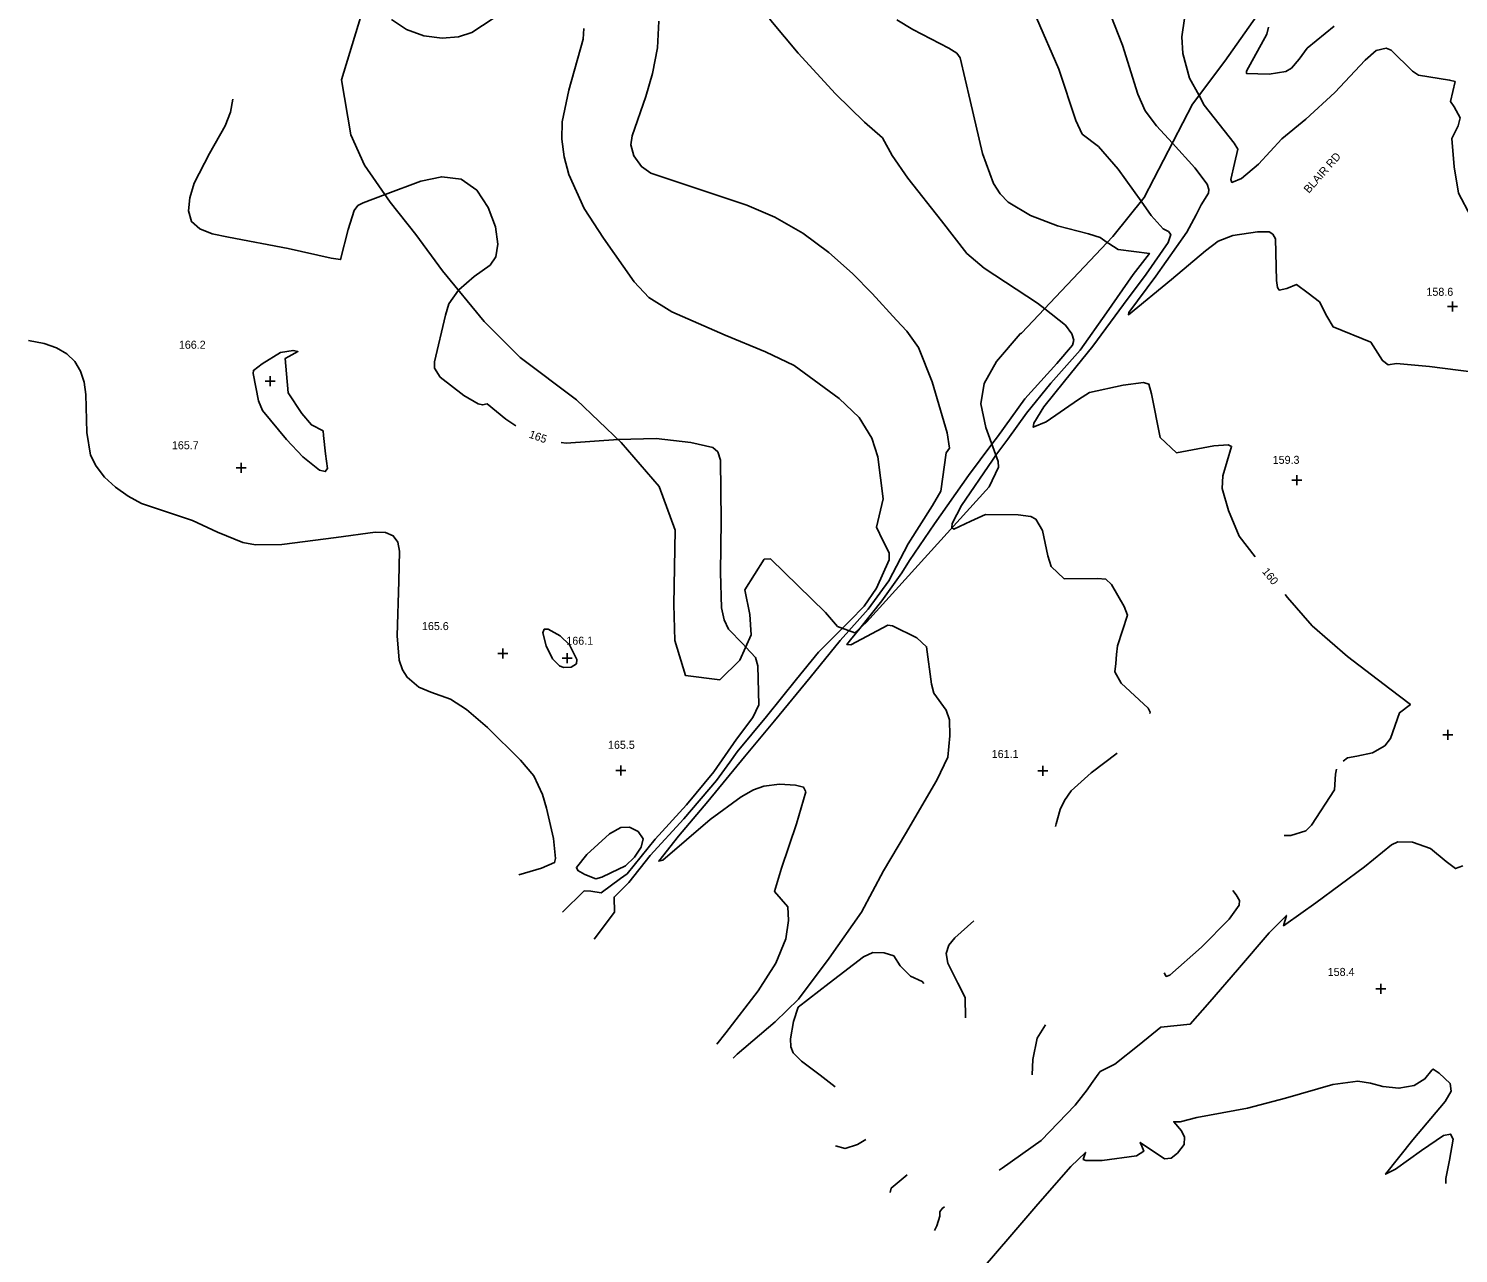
# Model space of a CAD drawing. Extents: x 1467615 to 2003689, y 770235 to 1108726.
# Drawn here: x 1999471.6 to 1999828.9, y 773778.4 to 774084.4 of the extents above; entities that cross this region are included whole.
import ezdxf

# ---------------------------------------------------------------- set-up
doc = ezdxf.new("R2010")
doc.units = 0
for name, color, linetype in [('RD_DTM_Major1', 7, 'Continuous'), ('RD_DTM_Major1_Lbl', 7, 'Continuous'), ('RD_DTM_Major2', 7, 'Continuous'), ('RD_DTM_Minor1', 7, 'Continuous'), ('RD_DTM_Minor2', 7, 'Continuous'), ('RD_DTM_Obscure', 7, 'Continuous'), ('RD_DTM_Spot_Elev', 7, 'Continuous'), ('RD_TX_Misc1', 7, 'Continuous')]:
    doc.layers.add(name, color=color, linetype=linetype)

msp = doc.modelspace()

# ---------------------------------------------------------------- linework, layer by layer
at = {"layer": 'RD_DTM_Major1'}
for points in [[(1999560.63, 774042.9), (1999555.19, 774040.85), (1999553.86, 774040.15), (1999552.92, 774038.92), (1999551.41, 774034.18), (1999549.52, 774026.68), (1999547.18, 774027.07), (1999536.41, 774029.44), (1999521.51, 774032.28), (1999517.47, 774033.14), (1999514.32, 774034.34), (1999512.28, 774036.16), (1999511.51, 774038.82), (1999511.82, 774042.11), (1999512.97, 774045.78), (1999516.74, 774053.17), (1999520.69, 774060.09), (1999522.04, 774063.47), (1999522.6, 774066.75)], [(1999778.05, 773952.38), (1999774.05, 773957.61), (1999771.41, 773963.97), (1999769.85, 773969.48), (1999770.01, 773972.67), (1999772.18, 773980), (1999771.29, 773980.41), (1999767.74, 773980.18), (1999758.4, 773978.41), (1999754.35, 773982.23), (1999752.14, 773993.16), (1999751.52, 773995.58), (1999750.16, 773995.97), (1999745.08, 773995.3), (1999736.71, 773993.46), (1999733.91, 773991.75), (1999725.87, 773986.14), (1999722.63, 773984.78), (1999722.72, 773985.79), (1999725.24, 773989.86), (1999730.41, 773996.34), (1999737.54, 774005.04), (1999745.14, 774015.42), (1999750.8, 774023.04), (1999756.29, 774030.91), (1999757.02, 774032.96), (1999756.43, 774033.66), (1999755.09, 774034.35), (1999752.09, 774037.68), (1999749.55, 774041.26)], [(1999593.35, 773985.11), (1999590.82, 773986.8), (1999586.18, 773990.62), (1999584.99, 773990.38), (1999583.93, 773990.61), (1999580.32, 773992.69), (1999574.4, 773997.32), (1999572.97, 773999.54), (1999573.01, 774001.13), (1999575.74, 774012.78), (1999576.54, 774015.63), (1999578.99, 774019.02)], [(1999618.88, 773981.75), (1999605.9, 773980.8), (1999604.61, 773980.97)], [(1999800.04, 773901.32), (1999801.16, 773902.2), (1999803.5, 773902.64), (1999807.4, 773903.44), (1999810.49, 773905.22), (1999811.85, 773907.01), (1999814.16, 773913.45), (1999816.85, 773915.49), (1999811.71, 773919.46), (1999801.14, 773927.52), (1999792.35, 773935.18), (1999786.15, 773942.23), (1999785.53, 773943)], [(1999604.96, 773863.63), (1999610.41, 773868.94), (1999612.1, 773868.89), (1999614.66, 773868.47), (1999619.46, 773872.03), (1999621.11, 773873.22), (1999628.11, 773881.84), (1999635.93, 773890.45), (1999642.78, 773898.71), (1999648.42, 773906.88), (1999652.58, 773912.29), (1999654.01, 773915.47), (1999653.82, 773925.2), (1999653.18, 773927.22), (1999650.77, 773929.87)], [(1999785.31, 773882.76), (1999786.95, 773882.82), (1999790.73, 773883.91), (1999792.17, 773885.38), (1999797.86, 773894.22), (1999798.18, 773898.09), (1999798.42, 773899.35)], [(1999755.34, 773848.44), (1999755.84, 773847.58), (1999756.73, 773847.88), (1999764.68, 773854.88), (1999771.61, 773861.91), (1999774.05, 773865.37), (1999774.19, 773866.55), (1999773.31, 773867.97), (1999772.51, 773869.08)], [(1999722.32, 773822.96), (1999722.48, 773826.78), (1999723.63, 773832.16), (1999725.71, 773835.45)], [(1999686.9, 773793.57), (1999687.11, 773794.67), (1999691.13, 773797.97)]]:
    msp.add_lwpolyline(points, dxfattribs=at)
at = {"layer": 'RD_DTM_Major2'}
for points in [[(1999749.55, 774041.26), (1999743.84, 774049.31), (1999738.9, 774054.96), (1999734.8, 774058.02), (1999733.29, 774061.4), (1999729.02, 774074.24), (1999723.4, 774087.09), (1999719.88, 774093.07), (1999716.04, 774097.99), (1999712.14, 774101.86), (1999705.4, 774106.94), (1999702.18, 774109.17)], [(1999578.99, 774019.02), (1999579.05, 774019.11), (1999582.88, 774022.47), (1999586.94, 774025.31), (1999588.32, 774027.38), (1999588.84, 774030.49), (1999588.21, 774034.84), (1999586.43, 774039.67), (1999583.55, 774043.99), (1999579.63, 774046.78), (1999574.82, 774047.36), (1999569.61, 774046.27), (1999560.63, 774042.9)], [(1999650.77, 773929.87), (1999650.04, 773930.68), (1999646.5, 773934.33), (1999645.38, 773936.67), (1999644.75, 773939.65), (1999644.44, 773948.5), (1999644.62, 773961.42), (1999644.44, 773976.59), (1999643.8, 773978.62), (1999642.51, 773979.69), (1999637.07, 773980.97), (1999628.41, 773981.96), (1999618.9, 773981.75), (1999618.88, 773981.75)]]:
    msp.add_lwpolyline(points, dxfattribs=at)
at = {"layer": 'RD_DTM_Minor1'}
for points in [[(1999797.8, 774084.97), (1999791.03, 774079.46), (1999789.04, 774076.75), (1999787.17, 774074.53), (1999785.7, 774073.7), (1999781.56, 774072.99), (1999775.88, 774073.21), (1999775.9, 774073.74), (1999781.01, 774082.98), (1999781.44, 774084.75)], [(1999832, 774037.43), (1999828.84, 774043.31), (1999827.81, 774049.87), (1999827.24, 774056.96), (1999828.79, 774060.09), (1999829.29, 774062.11), (1999827.8, 774064.88), (1999826.85, 774066.2), (1999828.02, 774071.17), (1999826.63, 774071.52), (1999818.89, 774072.79), (1999817.39, 774073.77), (1999812.04, 774078.98), (1999810.79, 774079.46), (1999808.31, 774078.88), (1999805.53, 774076.51), (1999797.97, 774068.44), (1999790.69, 774061.79), (1999784.77, 774056.83), (1999778.89, 774050.54), (1999774.67, 774046.9), (1999772.25, 774045.95), (1999772, 774046.7), (1999772.87, 774050.68), (1999773.72, 774054.26), (1999772.81, 774055.75), (1999765.3, 774065.3), (1999764.04, 774067.66)], [(1999832.74, 773998.56), (1999821.61, 773999.99), (1999813.35, 774000.7), (1999811.3, 774000.38), (1999809.9, 774001.45), (1999806.96, 774006.06), (1999797.56, 774009.87), (1999795.98, 774012.52), (1999794.11, 774016.11), (1999791.35, 774018.32), (1999788.38, 774020.45), (1999786, 774019.43), (1999784.09, 774019.04), (1999783.63, 774019.71), (1999783.38, 774021.49), (1999783.11, 774031.85), (1999782.5, 774033.01), (1999781.56, 774033.57), (1999778.67, 774033.59), (1999772.51, 774032.69), (1999768.81, 774031.25), (1999765.63, 774028.89), (1999757.12, 774021.72), (1999746.39, 774012.91), (1999746.46, 774013.43), (1999753.23, 774022.54), (1999761.02, 774033.52), (1999763.3, 774037.88), (1999764.61, 774040.36), (1999766.37, 774043.24), (1999766.48, 774044.22), (1999766.06, 774045.49), (1999763.02, 774049.59), (1999757.37, 774055.78)], [(1999713.3, 773977.77), (1999716.24, 773981.79), (1999720.93, 773988.3), (1999726.98, 773995.76), (1999734.33, 774004.07), (1999740.92, 774013.39), (1999747.58, 774022.91), (1999751.64, 774028.21), (1999743.87, 774029.16), (1999741.48, 774030.67), (1999741.09, 774030.96)], [(1999712.3, 773980.52), (1999713.71, 773982.38), (1999720.5, 773991.89), (1999728.53, 774000.69), (1999732.42, 774005.29), (1999732.74, 774006.54), (1999732.28, 774008.16), (1999730.64, 774010.28), (1999725.47, 774014.4)], [(1999594.08, 773872.94), (1999599.75, 773874.59), (1999603.01, 773876), (1999603.25, 773877.03), (1999602.72, 773882.03), (1999601, 773889.62), (1999599.98, 773893.06), (1999597.81, 773897.7), (1999594.48, 773901.59), (1999586.27, 773909.77), (1999581.01, 773914.28), (1999576.99, 773916.83), (1999572.07, 773918.63), (1999569.04, 773919.88), (1999566.18, 773922.33), (1999565.03, 773924.19), (1999564.2, 773926.57), (1999563.65, 773932.69), (1999564.08, 773946.33), (1999564.26, 773953.81), (1999563.8, 773956.05), (1999562.7, 773957.67), (1999560.78, 773958.47), (1999558.18, 773958.6), (1999548.42, 773957.22), (1999534.87, 773955.47), (1999528.29, 773955.43), (1999525.08, 773956.01), (1999518.77, 773958.56), (1999512.54, 773961.47), (1999499.8, 773965.71), (1999496.48, 773967.53), (1999493.32, 773969.79), (1999490.55, 773972.35), (1999488.42, 773975.05), (1999487.07, 773977.81), (1999486.12, 773983.51), (1999485.89, 773992.95), (1999485.43, 773996.03), (1999484.55, 773998.82), (1999483.12, 774001.2), (1999481.12, 774003.14), (1999478.57, 774004.64), (1999475.46, 774005.71), (1999471.57, 774006.43)], [(1999536.44, 773993.36), (1999536, 773998.11), (1999535.7, 774001.97), (1999536.56, 774002.5), (1999538.88, 774003.69), (1999537.67, 774003.99), (1999534.54, 774003.46), (1999529.95, 774000.65), (1999527.75, 773998.98), (1999527.67, 773998.24), (1999529, 773991.41), (1999530, 773988.93), (1999536, 773981.73), (1999540.06, 773977.39), (1999544.3, 773974.1), (1999545.68, 773973.72), (1999546.24, 773974.5), (1999545.79, 773978.15), (1999545.27, 773982.74), (1999545.16, 773983.87), (1999542.23, 773985.36), (1999539.84, 773988.26), (1999536.44, 773993.36)], [(1999751.74, 773913.28), (1999751.86, 773913.62), (1999751.31, 773914.58), (1999744.58, 773920.83), (1999742.97, 773923.66), (1999743.25, 773925.74), (1999743.38, 773928.01), (1999743.65, 773930.19), (1999746.13, 773937.86), (1999745.36, 773939.96), (1999742.17, 773945.49), (1999740.74, 773946.79), (1999738.71, 773947.03), (1999730.36, 773946.91), (1999727.12, 773950), (1999726.29, 773952.63), (1999724.95, 773959.01), (1999723.29, 773961.82), (1999722, 773962.52), (1999718.83, 773962.92), (1999710.72, 773963.01), (1999706.99, 773961.29), (1999702.75, 773959.36), (1999702.33, 773959.66)], [(1999605.2, 773924.77), (1999607.15, 773924.87), (1999608.47, 773925.69), (1999608.59, 773926.75), (1999606.75, 773930.45), (1999604.41, 773932.66), (1999601.43, 773934.35), (1999600.42, 773934.32), (1999600.07, 773933.44), (1999600.86, 773930.14), (1999602.47, 773926.96), (1999604.24, 773925.16), (1999605.2, 773924.77)], [(1999612.89, 773856.85), (1999617.94, 773863.63), (1999617.85, 773867.4), (1999620.12, 773869.65), (1999621.57, 773871.06), (1999626.91, 773877.75), (1999635.32, 773886.97), (1999643.45, 773896.54), (1999646.76, 773901.11), (1999648.59, 773903.69), (1999655.96, 773912.48), (1999663.43, 773921.88), (1999668.91, 773928.55), (1999674.97, 773934.56)], [(1999647.61, 773827.17), (1999648.6, 773828.18), (1999658.12, 773836.22), (1999663.99, 773841.92), (1999671.6, 773852.15), (1999679.7, 773863.64), (1999685.23, 773873.92), (1999690.71, 773883.16), (1999698.53, 773896.62), (1999701.24, 773902.36), (1999701.78, 773907.66), (1999701.71, 773911.7), (1999700.87, 773914.13), (1999697.77, 773918.37), (1999697.23, 773920.57), (1999695.94, 773929.96), (1999693.54, 773932.15), (1999687.41, 773935.17), (1999686.29, 773935.34), (1999677.03, 773930.43), (1999676.07, 773930.5), (1999676.98, 773931.64), (1999679.29, 773934.54)], [(1999643.51, 773830.67), (1999645.82, 773833.51), (1999653.88, 773843.94), (1999658.29, 773850.87), (1999660.79, 773856.95), (1999661.49, 773861.54), (1999661.29, 773865), (1999657.98, 773868.81), (1999659.7, 773874.58), (1999663.49, 773885.67), (1999665.76, 773893.73), (1999665.24, 773894.84), (1999663.24, 773895.33), (1999659.2, 773895.61), (1999655.31, 773895.12), (1999652.75, 773894.17), (1999649.64, 773892.47), (1999641.9, 773886.75), (1999630.03, 773876.62), (1999629.04, 773876.38), (1999633.93, 773882.58), (1999641.26, 773891.24), (1999650.44, 773902.41), (1999657.98, 773911.4), (1999666.83, 773922.29), (1999674.39, 773931.53), (1999676.57, 773933.95)], [(1999728.18, 773885.04), (1999728.34, 773885.68), (1999729.33, 773889.28), (1999730.43, 773891.55), (1999732.12, 773893.92), (1999737.11, 773898.42), (1999743.56, 773903.32)], [(1999610.53, 773873.06), (1999613.34, 773871.95), (1999614.81, 773872.37), (1999617.1, 773873.42), (1999620.71, 773875.23), (1999623.01, 773877.41), (1999624.66, 773879.84), (1999625.12, 773881.97), (1999623.88, 773883.79), (1999621.73, 773884.87), (1999619.55, 773884.82), (1999616.75, 773883.17), (1999611.07, 773878.03), (1999608.46, 773874.79), (1999608.8, 773874.01), (1999610.53, 773873.06)], [(1999714.06, 773799.15), (1999714.82, 773799.63), (1999724.63, 773806.61), (1999733.06, 773815.44), (1999736.08, 773819.27), (1999737.16, 773820.83), (1999738.8, 773823.11), (1999739.3, 773823.79), (1999743, 773825.67), (1999749.06, 773830.49), (1999754.53, 773834.88), (1999761.83, 773835.65), (1999766.71, 773841.21), (1999773.62, 773849.25), (1999781.53, 773858.43), (1999785.88, 773862.81), (1999785.19, 773860.24), (1999785.76, 773860.61), (1999793.2, 773865.94), (1999805.41, 773874.92), (1999812.12, 773880.47), (1999813.75, 773881.18), (1999817.37, 773881.1), (1999821.86, 773879.56), (1999825.79, 773876.32), (1999828.14, 773874.53), (1999830, 773875.21)], [(1999705.69, 773837.2), (1999705.57, 773842.31), (1999703.8, 773845.9), (1999701.3, 773850.89), (1999700.88, 773853.31), (1999701.52, 773855.39), (1999703, 773857.21), (1999707.74, 773861.44)], [(1999695.27, 773845.78), (1999694.89, 773846.29), (1999691.93, 773847.64), (1999689.35, 773850.23), (1999687.74, 773852.7), (1999685.36, 773853.48), (1999682.53, 773853.56), (1999680.17, 773852.44), (1999671.64, 773845.87), (1999663.85, 773839.89), (1999662.74, 773836.31), (1999661.95, 773831.97), (1999662.02, 773830), (1999662.58, 773828.47), (1999664.71, 773826.43), (1999669.39, 773822.94), (1999673.15, 773819.97)], [(1999709.59, 773774.18), (1999717.25, 773783.06), (1999723.74, 773790.64), (1999731.97, 773800.11), (1999735.7, 773803.59), (1999735.12, 773801.84), (1999735.79, 773801.56), (1999739.87, 773801.56), (1999748.44, 773802.73), (1999750.28, 773803.93), (1999749.76, 773805.16), (1999749.34, 773806.1), (1999755.4, 773801.97), (1999757.07, 773802.18), (1999758.67, 773803.42), (1999760.33, 773805.6), (1999760.44, 773807.4), (1999759.64, 773808.98), (1999757.72, 773811.26), (1999759.36, 773811.26), (1999763.51, 773812.34), (1999776.19, 773814.63), (1999785.61, 773817.16), (1999797.48, 773820.53), (1999803.73, 773821.4), (1999806.86, 773820.87), (1999809.94, 773820.03), (1999813.98, 773819.64), (1999817.82, 773820.35), (1999820.47, 773821.98), (1999822.22, 773824.16), (1999822.57, 773824.43), (1999824.03, 773823.43), (1999826.79, 773820.8), (1999827.02, 773818.94), (1999825.51, 773816.31), (1999817.45, 773806.77), (1999810.64, 773798.14), (1999813.16, 773799.42), (1999819.63, 773804.11), (1999825.13, 773807.82), (1999826.9, 773808.18), (1999827.51, 773806.92), (1999826.59, 773801.65), (1999825.75, 773797.11), (1999825.7, 773795.83)], [(1999673.24, 773805.26), (1999675.62, 773804.61), (1999678.66, 773805.54), (1999680.79, 773806.82)], [(1999697.96, 773784.12), (1999698.5, 773785.22), (1999699.28, 773787.71), (1999699.28, 773788.74), (1999699.88, 773789.61), (1999700.41, 773790.02)]]:
    msp.add_lwpolyline(points, dxfattribs=at)
at = {"layer": 'RD_DTM_Minor2'}
for points in [[(1999725.47, 774014.4), (1999723.69, 774015.83), (1999710.39, 774024.54), (1999706.01, 774028.2), (1999699.65, 774036.37), (1999691.26, 774047.01), (1999687.39, 774052.7), (1999684.95, 774057.09), (1999680.46, 774061.03), (1999673.23, 774068.13), (1999663.86, 774078.28), (1999657.01, 774086.4), (1999653.43, 774092.06), (1999647.74, 774104.43), (1999640.9, 774118.93), (1999636.16, 774126.49), (1999633.18, 774129.85), (1999625.81, 774136.1), (1999619.01, 774141.59), (1999616.76, 774144.07), (1999615.23, 774146.92), (1999614.17, 774150.74), (1999612.53, 774163.5), (1999611.77, 774172.12)], [(1999757.37, 774055.78), (1999753.43, 774060.09), (1999750.57, 774063.86), (1999748.72, 774067.97), (1999744.88, 774080.24), (1999740.04, 774092.84)], [(1999590.53, 774088.84), (1999582.3, 774083.42), (1999578.99, 774082.34), (1999574.87, 774082.04), (1999570.34, 774082.61), (1999565.96, 774084.13), (1999562.28, 774086.64)], [(1999674.97, 773934.56), (1999676.8, 773936.38), (1999680.34, 773940.1), (1999683.41, 773944.56), (1999686.59, 773951.68), (1999686.6, 773953.38), (1999685.06, 773956.53), (1999683.45, 773959.83), (1999685.11, 773966.94), (1999683.79, 773977.4), (1999682.29, 773982.04), (1999679.13, 773987.2), (1999674.15, 773991.93), (1999662.9, 774000.2), (1999655.71, 774003.65), (1999645.6, 774007.82), (1999632.28, 774013.64), (1999626.53, 774017.23), (1999622.92, 774021.16), (1999615.19, 774032.02), (1999610.38, 774039.41), (1999606.6, 774047.92), (1999605.4, 774052.36), (1999604.83, 774056.78), (1999604.93, 774061.06), (1999606.53, 774069.03), (1999610.18, 774081.71), (1999610.31, 774084.4)], [(1999676.57, 773933.95), (1999681.39, 773939.3), (1999686.56, 773946.4), (1999691.33, 773955.68), (1999697.48, 773965.22), (1999699.48, 773968.81), (1999700.88, 773978.39), (1999701.65, 773979.54), (1999701.11, 773983.39), (1999697.36, 773996.15), (1999693.97, 774004.72), (1999691.02, 774008.77), (1999688.43, 774011.53), (1999682.34, 774018.23), (1999677.43, 774023.21), (1999671.57, 774028.46), (1999665, 774033.31), (1999658.01, 774037.25), (1999651.01, 774040.3), (1999638.84, 774044.34), (1999627.06, 774048.25), (1999624.69, 774049.92), (1999622.8, 774052.64), (1999622.06, 774055.35), (1999622.4, 774057.56), (1999625.79, 774067.42), (1999627.47, 774073.15), (1999628.72, 774079.58), (1999629.03, 774086.28)], [(1999741.09, 774030.96), (1999739.37, 774032.21), (1999736.4, 774033.09), (1999728.66, 774035.08), (1999721.9, 774037.73), (1999716.36, 774041.06), (1999714.36, 774043.11), (1999712.72, 774045.69), (1999709.97, 774053.2), (1999706.89, 774066.41), (1999704.36, 774077.1), (1999703.56, 774078.25), (1999701.51, 774079.54), (1999692.51, 774084.13), (1999688.51, 774086.62)], [(1999764.04, 774067.66), (1999761.69, 774072.04), (1999759.97, 774078.13), (1999759.74, 774082.36), (1999760.4, 774086.89)], [(1999679.29, 773934.54), (1999684.76, 773941.42), (1999689.79, 773948.44), (1999691.68, 773951.51), (1999697.95, 773960.67), (1999706.45, 773972.76), (1999712.3, 773980.52)], [(1999702.33, 773959.66), (1999702.25, 773959.71), (1999702.37, 773960.77), (1999704.72, 773965.26), (1999712.44, 773976.59), (1999713.3, 773977.77)]]:
    msp.add_lwpolyline(points, dxfattribs=at)
at = {"layer": 'RD_DTM_Obscure'}
msp.add_lwpolyline([(1999778.48, 774087.59), (1999770.49, 774076.22), (1999762.45, 774065.54), (1999750.29, 774042.19), (1999742.52, 774032.47), (1999719.71, 774008.3), (1999719.32, 774008.13), (1999713.46, 774001.19), (1999710.31, 773995.71), (1999709.5, 773990.65), (1999710.75, 773984.69), (1999712.88, 773978.96), (1999713.86, 773976.19), (1999713.96, 773974.84), (1999711.61, 773969.88), (1999680.94, 773936.09), (1999678.07, 773933.39), (1999673.74, 773935.02), (1999670.69, 773938.5), (1999656.93, 773951.92), (1999655.39, 773951.82), (1999650.55, 773944.15), (1999651.79, 773938), (1999652.12, 773932.88), (1999649.31, 773926.61), (1999644.27, 773921.65), (1999635.68, 773922.79), (1999633.07, 773931.53), (1999632.79, 773940.5), (1999633.14, 773959.05), (1999629.14, 773969.99), (1999619.66, 773981), (1999608.52, 773991.64), (1999594.4, 774002.18), (1999585.37, 774011.24), (1999575.03, 774023.84), (1999568.32, 774032.94), (1999561.92, 774041.06), (1999555.5, 774050.23), (1999552.05, 774057.86), (1999549.78, 774071.58), (1999554.54, 774087.14)], dxfattribs=at)
at = {"layer": 'RD_DTM_Spot_Elev'}
for p, q in [((1999826.13, 774014.92), (1999828.63, 774014.92)), ((1999827.38, 774013.67), (1999827.38, 774016.17)), ((1999530.69, 773996.29), (1999533.19, 773996.29)), ((1999531.94, 773995.04), (1999531.94, 773997.54)), ((1999523.44, 773974.64), (1999525.94, 773974.64)), ((1999524.69, 773973.39), (1999524.69, 773975.89)), ((1999787.22, 773971.6), (1999789.72, 773971.6)), ((1999788.47, 773970.35), (1999788.47, 773972.85)), ((1999588.81, 773928.28), (1999591.31, 773928.28)), ((1999590.06, 773927.03), (1999590.06, 773929.53)), ((1999606.15, 773925.8), (1999606.15, 773928.3)), ((1999604.9, 773927.05), (1999607.4, 773927.05)), ((1999826.24, 773906.72), (1999826.24, 773909.22)), ((1999824.99, 773907.97), (1999827.49, 773907.97)), ((1999618.29, 773899.01), (1999620.79, 773899.01)), ((1999619.54, 773897.76), (1999619.54, 773900.26)), ((1999723.72, 773898.91), (1999726.22, 773898.91)), ((1999724.97, 773897.66), (1999724.97, 773900.16)), ((1999809.43, 773843.23), (1999809.43, 773845.73)), ((1999808.18, 773844.48), (1999810.68, 773844.48))]:
    msp.add_line(p, q, dxfattribs=at)

# ---------------------------------------------------------------- texts
at = {"layer": 'RD_DTM_Major1_Lbl'}
for s, rotation, p in [('165', 340.4626, (1999596.44, 773982.24)), ('160', 308.7553, (1999779.68, 773948.69))]:
    msp.add_text(s, height=2, rotation=rotation, dxfattribs=at).set_placement(p)
at = {"layer": 'RD_DTM_Spot_Elev'}
for s, p in [('158.6', (1999820.87, 774017.63)), ('166.2', (1999509.12, 774004.4)), ('165.7', (1999507.38, 773979.29)), ('159.3', (1999782.45, 773975.64)), ('165.6', (1999569.86, 773934.11)), ('166.1', (1999605.94, 773930.45)), ('165.5', (1999616.35, 773904.44)), ('161.1', (1999712.24, 773902.15)), ('158.4', (1999796.2, 773847.7))]:
    msp.add_text(s, height=2, dxfattribs=at).set_placement(p)
at = {"layer": 'RD_TX_Misc1'}
msp.add_text('BLAIR RD', height=2, rotation=48.6914, dxfattribs=at).set_placement((1999791.49, 774043.09))

doc.saveas('drawing.dxf')
